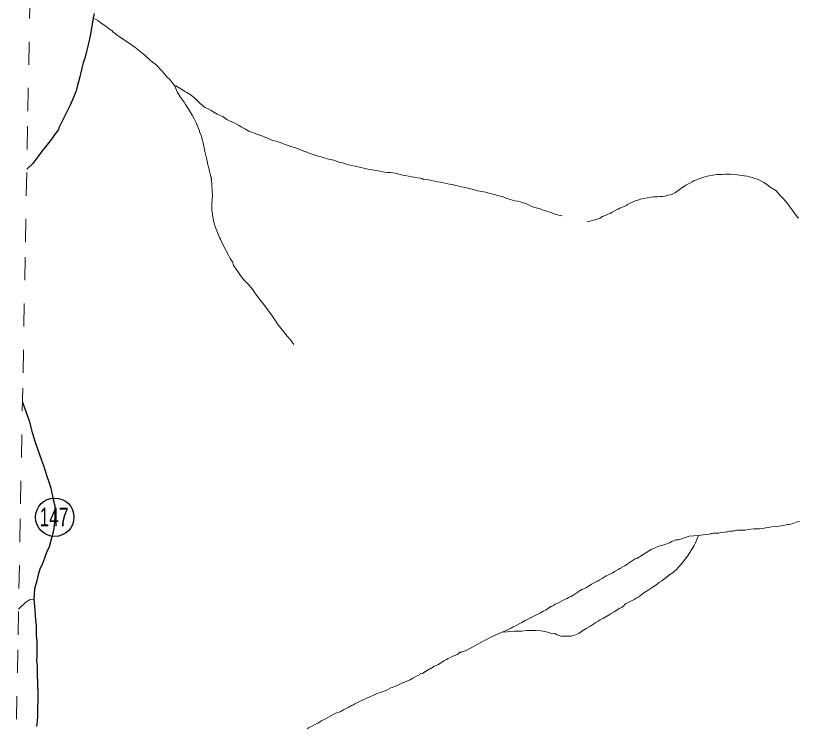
# Model space of a CAD drawing. Extents: x 781.9 to 808.1, y 7453.3 to 7481.5.
# Drawn here: x 782.028 to 785.41, y 7460.198 to 7463.258 of the extents above; entities that cross this region are included whole.
import ezdxf
from ezdxf.enums import TextEntityAlignment as Align

# ---------------------------------------------------------------- set-up
doc = ezdxf.new("R2010")
doc.units = 0
doc.header["$LTSCALE"] = 0.032
for name, pattern in [('DOTTED', [1.5, 0.3, -1.2]), ('LONG_DASHED', [7.5, 6, -1.5]), ('MEDIUM_DASHED', [4.5, 3, -1.5]), ('SHORT_DASHED', [2.7, 1.5, -1.2])]:
    doc.linetypes.add(name, pattern=pattern)
for name, color, linetype, lineweight in [('13', 7, 'Continuous', 25), ('35', 7, 'SHORT_DASHED', 13), ('4', 7, 'LONG_DASHED', 25), ('5', 7, 'LONG_DASHED', 13), ('6', 7, 'MEDIUM_DASHED', 13), ('7', 7, 'DOTTED', 13)]:
    doc.layers.add(name, color=color, linetype=linetype, lineweight=lineweight)
doc.layers.add('61', color=7, linetype='Continuous')

msp = doc.modelspace()

# ---------------------------------------------------------------- linework, layer by layer
at = {"layer": '13'}
msp.add_circle((782.1971, 7461.0924), 0.083, dxfattribs=at)
msp.add_circle((782.1971, 7461.0924), 0.083, dxfattribs=at)
msp.add_circle((782.1971, 7461.0924), 0.083, dxfattribs=at)
at = {"layer": '35'}
msp.add_lwpolyline([(782.0281, 7460.0199), (782.0387, 7460.5852), (782.0493, 7461.1504), (782.0599, 7461.7157), (782.0704, 7462.2809), (782.081, 7462.8462), (782.0916, 7463.4115), (782.1022, 7463.9767), (782.1127, 7464.542), (782.1233, 7465.1072), (782.1339, 7465.6725), (782.1444, 7466.2377), (782.155, 7466.803), (782.1655, 7467.3682)], dxfattribs=at)
at = {"layer": '4'}
for points in [[(782.367, 7463.2683), (782.3634, 7463.2487)], [(782.3634, 7463.2487), (782.3518, 7463.1787), (782.3451, 7463.1517), (782.3402, 7463.1274), (782.3337, 7463.1031), (782.328, 7463.0788), (782.3199, 7463.0545), (782.3134, 7463.0318), (782.3078, 7463.0074), (782.3021, 7462.9831), (782.2948, 7462.9588), (782.2891, 7462.9345), (782.281, 7462.9118), (782.2634, 7462.8726), (782.2482, 7462.8406), (782.2154, 7462.7742), (782.2137, 7462.7666), (782.2064, 7462.7569), (782.1991, 7462.748), (782.1829, 7462.7245), (782.1634, 7462.6993), (782.1432, 7462.6742), (782.1237, 7462.6482), (782.1026, 7462.6207), (782.0763, 7462.5962)], [(782.0575, 7461.5895), (782.0724, 7461.5495), (782.086, 7461.5087), (782.0988, 7461.4583), (782.1132, 7461.4119), (782.1221, 7461.3875), (782.131, 7461.3632), (782.1391, 7461.3389), (782.148, 7461.3162), (782.1562, 7461.2935), (782.1634, 7461.2692), (782.1715, 7461.2448), (782.1797, 7461.2177), (782.1909, 7461.1697), (782.1973, 7461.1417), (782.1981, 7461.0913), (782.1949, 7461.0585), (782.1916, 7461.0337), (782.1836, 7461.0019), (782.1723, 7460.9643), (782.1618, 7460.94), (782.1529, 7460.9157), (782.1448, 7460.893), (782.1326, 7460.8686), (782.1253, 7460.8443), (782.1189, 7460.8183), (782.11, 7460.7831), (782.106, 7460.7383)], [(782.106, 7460.7383), (782.1116, 7460.6903), (782.1131, 7460.6692), (782.114, 7460.6481), (782.1172, 7460.627), (782.1172, 7460.606), (782.1164, 7460.5881), (782.1164, 7460.5816), (782.1189, 7460.5573), (782.1189, 7460.5346), (782.1189, 7460.5135), (782.1189, 7460.4924), (782.118, 7460.4714), (782.1205, 7460.4503), (782.1213, 7460.4276), (782.1213, 7460.4049), (782.1221, 7460.3838), (782.1229, 7460.3627), (782.1245, 7460.3416), (782.1237, 7460.3189), (782.1237, 7460.2962), (782.1229, 7460.2752), (782.1221, 7460.2541), (782.1229, 7460.233), (782.1205, 7460.2119), (782.118, 7460.1892)]]:
    msp.add_lwpolyline(points, dxfattribs=at)
at = {"layer": '5'}
msp.add_lwpolyline([(782.106, 7460.7383), (782.0907, 7460.7367), (782.0721, 7460.7258), (782.0408, 7460.6955)], dxfattribs=at)
at = {"layer": '6'}
for points in [[(782.3634, 7463.2487), (782.3834, 7463.2375), (782.4018, 7463.2239), (782.4172, 7463.2125), (782.4326, 7463.202), (782.4399, 7463.1963), (782.4432, 7463.1939), (782.4488, 7463.1874), (782.4504, 7463.1874), (782.4683, 7463.1728), (782.4837, 7463.1623), (782.4991, 7463.1525), (782.5137, 7463.1428), (782.5291, 7463.1331), (782.5437, 7463.1225), (782.564, 7463.1055), (782.5859, 7463.0877), (782.5923, 7463.082), (782.6061, 7463.0698), (782.6199, 7463.0577), (782.6337, 7463.048), (782.6617, 7463.0194), (782.6833, 7462.9922), (782.6928, 7462.9838), (782.7145, 7462.9565)], [(782.7145, 7462.9565), (782.7269, 7462.9264), (782.7431, 7462.9028), (782.7569, 7462.885), (782.7626, 7462.8745), (782.7731, 7462.8583), (782.7829, 7462.8437), (782.7909, 7462.8291), (782.7991, 7462.8136), (782.8088, 7462.7958), (782.821, 7462.7634), (782.8242, 7462.7545), (782.8307, 7462.7383), (782.8339, 7462.7237), (782.838, 7462.7091), (782.8412, 7462.6945), (782.8453, 7462.6718), (782.8534, 7462.6434), (782.8558, 7462.6296), (782.8582, 7462.615), (782.8632, 7462.6004), (782.8664, 7462.5858), (782.8696, 7462.5712), (782.8712, 7462.5615), (782.8745, 7462.5591), (782.8745, 7462.5534), (782.8736, 7462.5526), (782.8753, 7462.5356), (782.8761, 7462.5299), (782.8777, 7462.5031), (782.8793, 7462.4788), (782.8777, 7462.4626), (782.8761, 7462.4464), (782.8761, 7462.4318), (782.8761, 7462.4172), (782.8785, 7462.4026), (782.8794, 7462.3985), (782.885, 7462.3669), (782.8915, 7462.3442), (782.8972, 7462.3296), (782.9036, 7462.315), (782.9093, 7462.3004), (782.9126, 7462.2931), (782.9256, 7462.2648), (782.9393, 7462.2405), (782.9483, 7462.2242), (782.9555, 7462.2096), (782.9645, 7462.195), (782.9693, 7462.1805), (782.9693, 7462.1796), (782.9888, 7462.1537), (783.0026, 7462.1318), (783.0147, 7462.1172), (783.0334, 7462.0986), (783.0496, 7462.0783), (783.0618, 7462.0621), (783.082, 7462.0345), (783.1001, 7462.0108), (783.137, 7461.9619), (783.1623, 7461.9238), (783.1907, 7461.887), (783.2012, 7461.8748), (783.2166, 7461.8578), (783.2263, 7461.8448), (783.2304, 7461.8391)], [(782.7145, 7462.9565), (782.7209, 7462.9554), (782.7353, 7462.9474), (782.7538, 7462.9356), (782.7624, 7462.9297), (782.7675, 7462.9271), (782.7869, 7462.9158), (782.8039, 7462.9004), (782.812, 7462.8923), (782.8243, 7462.8801), (782.8372, 7462.8696), (782.8469, 7462.8623), (782.8599, 7462.8558), (782.8729, 7462.8493), (782.885, 7462.8412), (782.8988, 7462.8331), (782.9223, 7462.8234), (782.9296, 7462.8185), (782.9409, 7462.8104), (782.9507, 7462.8047), (782.9637, 7462.7998), (782.9774, 7462.7925), (782.9904, 7462.7853), (783.0026, 7462.7788), (783.022, 7462.769), (783.0358, 7462.7601), (783.0399, 7462.7585), (783.0529, 7462.7536), (783.0658, 7462.7488), (783.0788, 7462.7439), (783.0918, 7462.739), (783.1048, 7462.7334), (783.1177, 7462.7293), (783.1323, 7462.7228), (783.1526, 7462.7164), (783.1631, 7462.7131), (783.1761, 7462.7099), (783.1891, 7462.7042), (783.2053, 7462.6985), (783.2166, 7462.6936), (783.2328, 7462.6888), (783.2442, 7462.6847), (783.2637, 7462.6782), (783.2807, 7462.671), (783.2831, 7462.6701), (783.2961, 7462.6653), (783.3091, 7462.6604), (783.322, 7462.6563), (783.335, 7462.6523), (783.348, 7462.649), (783.361, 7462.6442), (783.3804, 7462.6393), (783.4023, 7462.6345), (783.4145, 7462.6304), (783.4274, 7462.6247), (783.4404, 7462.6223), (783.4534, 7462.6182), (783.4664, 7462.615), (783.4793, 7462.6117), (783.4955, 7462.6085), (783.5134, 7462.6036), (783.5385, 7462.5988), (783.5442, 7462.5972), (783.5572, 7462.5947), (783.5701, 7462.5923), (783.5831, 7462.5898), (783.5961, 7462.5882), (783.609, 7462.585), (783.622, 7462.5826), (783.635, 7462.5817), (783.648, 7462.5809)], [(783.648, 7462.5809), (783.6674, 7462.5785), (783.6958, 7462.5712), (783.6999, 7462.5704), (783.7128, 7462.568), (783.7258, 7462.5655), (783.7388, 7462.5631)], [(783.7388, 7462.5631), (783.7517, 7462.5615), (783.7647, 7462.5582), (783.7777, 7462.5574), (783.7834, 7462.555), (783.785, 7462.5542), (783.7866, 7462.5526), (783.7923, 7462.5517), (783.8206, 7462.5477), (783.8247, 7462.5469), (783.8377, 7462.5436), (783.8507, 7462.5412), (783.8636, 7462.5388), (783.8766, 7462.5372), (783.8896, 7462.5339), (783.9025, 7462.5315), (783.9155, 7462.529), (783.9298, 7462.5255), (783.9818, 7462.5135), (784.0002, 7462.5087), (784.0258, 7462.5023), (784.042, 7462.4991), (784.0582, 7462.4958), (784.0728, 7462.4918), (784.0955, 7462.4861), (784.1223, 7462.4796), (784.1344, 7462.4755), (784.1506, 7462.4691), (784.1669, 7462.465), (784.1831, 7462.4593), (784.1977, 7462.4577), (784.2123, 7462.4537), (784.235, 7462.4455), (784.2617, 7462.4334), (784.2771, 7462.4285), (784.2941, 7462.4236), (784.3079, 7462.418), (784.3225, 7462.4139), (784.3411, 7462.4082), (784.3598, 7462.4018), (784.3809, 7462.3961), (784.3898, 7462.3937)], [(785.4113, 7462.3839), (785.4049, 7462.3904), (785.387, 7462.4155), (785.3741, 7462.4326), (785.3635, 7462.448), (785.3554, 7462.4569), (785.3441, 7462.4691), (785.3327, 7462.4804), (785.3246, 7462.4901), (785.3125, 7462.5039), (785.2881, 7462.5185), (785.2727, 7462.5307), (785.2606, 7462.538), (785.2484, 7462.5453), (785.2378, 7462.5509), (785.2225, 7462.5558), (785.2111, 7462.5591), (785.1998, 7462.5631), (785.1884, 7462.5647), (785.177, 7462.5663), (785.1746, 7462.5664), (785.1479, 7462.5712), (785.13, 7462.5728), (785.1171, 7462.5745), (785.1041, 7462.5745), (785.0927, 7462.5745), (785.0814, 7462.5728), (785.07, 7462.572), (785.0587, 7462.572), (785.0498, 7462.5712), (785.0165, 7462.5655), (785.0019, 7462.5607), (784.9938, 7462.5582), (784.9809, 7462.5542), (784.9695, 7462.5501), (784.959, 7462.5453), (784.9508, 7462.5404), (784.9419, 7462.5356), (784.933, 7462.5307), (784.9241, 7462.5258), (784.92, 7462.5234), (784.8965, 7462.5071), (784.8795, 7462.4942), (784.8682, 7462.4885), (784.8576, 7462.4853), (784.8463, 7462.4828), (784.8349, 7462.4796), (784.8236, 7462.478), (784.8122, 7462.4772), (784.8009, 7462.4763), (784.7879, 7462.4763), (784.7838, 7462.4756), (784.7587, 7462.4723), (784.7393, 7462.4691), (784.7279, 7462.4658), (784.7166, 7462.4618), (784.7052, 7462.4585), (784.6939, 7462.4537), (784.6825, 7462.4488), (784.6727, 7462.4423), (784.6671, 7462.4383), (784.6436, 7462.4293), (784.6379, 7462.4277), (784.6314, 7462.4228), (784.6257, 7462.4212), (784.616, 7462.4155), (784.6063, 7462.4099), (784.5965, 7462.4042), (784.5868, 7462.4009), (784.5755, 7462.3953), (784.5641, 7462.3912), (784.552, 7462.3847), (784.5406, 7462.3791), (784.5155, 7462.3726), (784.496, 7462.3685)]]:
    msp.add_lwpolyline(points, dxfattribs=at)
at = {"layer": '7'}
for points in [[(785.4154, 7461.0745), (785.4057, 7461.0721), (785.3911, 7461.0664), (785.3724, 7461.0616), (785.3668, 7461.0608), (785.3571, 7461.0591), (785.3473, 7461.0567), (785.336, 7461.0551), (785.3198, 7461.0527), (785.2946, 7461.0503), (785.2792, 7461.0478), (785.2679, 7461.047), (785.2581, 7461.0445), (785.2419, 7461.0421), (785.2184, 7461.0429), (785.2046, 7461.0413), (785.1933, 7461.0389), (785.1811, 7461.0368), (785.1438, 7461.0364), (785.1365, 7461.0332), (785.13, 7461.0332), (785.1244, 7461.0324), (785.1187, 7461.0316), (785.1122, 7461.0316), (785.1057, 7461.0299), (785.1024, 7461.0292), (785.0992, 7461.0291), (785.0919, 7461.0275), (785.0733, 7461.0259), (785.0668, 7461.0243), (785.0619, 7461.0235), (785.0555, 7461.0235), (785.049, 7461.0235), (785.0425, 7461.0235), (785.036, 7461.0218), (785.0343, 7461.0226), (785.0327, 7461.021), (785.0295, 7461.021), (785.0254, 7461.0194), (785.0084, 7461.0178), (784.9783, 7461.0134)], [(784.9783, 7461.0134), (784.9646, 7460.9797), (784.9597, 7460.9708), (784.9516, 7460.9554), (784.9387, 7460.9359), (784.9338, 7460.9286), (784.9273, 7460.9189), (784.9152, 7460.9043), (784.903, 7460.8889), (784.8949, 7460.88), (784.8819, 7460.8654), (784.8649, 7460.8516), (784.8625, 7460.85), (784.8544, 7460.8451), (784.839, 7460.8321), (784.8211, 7460.8192), (784.8203, 7460.8184), (784.8098, 7460.8118), (784.7944, 7460.7997), (784.7741, 7460.7859), (784.766, 7460.781), (784.7571, 7460.7745), (784.7425, 7460.7656), (784.7206, 7460.7486), (784.7101, 7460.7429), (784.7036, 7460.7389), (784.7003, 7460.7373), (784.6979, 7460.7358), (784.6638, 7460.7186), (784.659, 7460.7138), (784.6565, 7460.7113), (784.6557, 7460.7089), (784.65, 7460.7073), (784.65, 7460.7064), (784.6468, 7460.7024), (784.6403, 7460.7), (784.6395, 7460.7), (784.6144, 7460.6837), (784.6014, 7460.6773), (784.5933, 7460.6716), (784.586, 7460.6667), (784.5681, 7460.6562), (784.5544, 7460.6497), (784.5448, 7460.644), (784.5349, 7460.6375), (784.5309, 7460.6351), (784.509, 7460.6213), (784.496, 7460.614), (784.4887, 7460.6084), (784.4814, 7460.6051), (784.479, 7460.6035), (784.4612, 7460.5905), (784.4474, 7460.5848), (784.4376, 7460.5816), (784.4279, 7460.5783), (784.4182, 7460.5784), (784.4141, 7460.5784), (784.3906, 7460.5783), (784.3858, 7460.5783), (784.3793, 7460.58), (784.3768, 7460.5824), (784.3728, 7460.5832), (784.3695, 7460.584), (784.3679, 7460.5849), (784.3647, 7460.5865), (784.3574, 7460.5897), (784.3387, 7460.5921), (784.3258, 7460.5962), (784.316, 7460.5986), (784.3063, 7460.6002), (784.2974, 7460.6019), (784.2755, 7460.6027), (784.2609, 7460.6027), (784.2528, 7460.6027), (784.2447, 7460.6027), (784.2374, 7460.6027), (784.2139, 7460.6011), (784.2009, 7460.601), (784.1912, 7460.6011), (784.1839, 7460.6011), (784.1514, 7460.5975), (784.1311, 7460.596)], [(784.9783, 7461.0134), (784.9382, 7461.0102), (784.8929, 7460.9954), (784.8884, 7460.9951), (784.8836, 7460.9951), (784.8827, 7460.9951), (784.8625, 7460.987), (784.8543, 7460.9821), (784.8495, 7460.9805), (784.8414, 7460.9772), (784.8333, 7460.9748), (784.8244, 7460.9724), (784.8074, 7460.9675), (784.7968, 7460.9635), (784.7911, 7460.961), (784.783, 7460.9578), (784.7749, 7460.9529), (784.7668, 7460.9481), (784.7579, 7460.9432), (784.7393, 7460.931), (784.7279, 7460.9237), (784.7198, 7460.9189), (784.7125, 7460.914), (784.7052, 7460.9132), (784.7044, 7460.9124), (784.6792, 7460.8954), (784.6663, 7460.8872), (784.6598, 7460.8832), (784.6517, 7460.8783), (784.642, 7460.8727), (784.6347, 7460.8686), (784.616, 7460.8581), (784.6055, 7460.8508), (784.5982, 7460.8475), (784.5901, 7460.8435), (784.582, 7460.8402), (784.5795, 7460.8395), (784.5625, 7460.8281), (784.5495, 7460.8208), (784.5422, 7460.8159), (784.5333, 7460.8127), (784.5252, 7460.8078), (784.5171, 7460.8029), (784.5147, 7460.8013), (784.4952, 7460.7892), (784.4831, 7460.7835), (784.4749, 7460.7802), (784.4668, 7460.7754), (784.4595, 7460.7705), (784.4579, 7460.7689)], [(784.4579, 7460.7689), (784.44, 7460.7575), (784.4279, 7460.7502), (784.4198, 7460.747), (784.4109, 7460.7421), (784.402, 7460.7381), (784.3995, 7460.7365)], [(784.3995, 7460.7365), (784.3793, 7460.7259), (784.3679, 7460.7202), (784.3598, 7460.717), (784.3517, 7460.7113), (784.3436, 7460.7073), (784.3412, 7460.7065), (784.3209, 7460.6927), (784.3079, 7460.6862), (784.3006, 7460.6821), (784.2917, 7460.6773), (784.282, 7460.6724), (784.2723, 7460.6675), (784.2698, 7460.6667), (784.2496, 7460.6562), (784.2382, 7460.6505), (784.2301, 7460.6464), (784.2228, 7460.6416), (784.2155, 7460.6383), (784.2131, 7460.6368), (784.1912, 7460.6246), (784.1782, 7460.6189), (784.1693, 7460.614), (784.1612, 7460.6092), (784.1311, 7460.596)], [(784.1311, 7460.596), (784.0902, 7460.5783), (784.0352, 7460.5506), (783.977, 7460.5189), (783.9589, 7460.5105), (783.9576, 7460.5119), (783.9552, 7460.5102), (783.9504, 7460.5102), (783.9496, 7460.5086), (783.9455, 7460.5078), (783.9423, 7460.5046), (783.9374, 7460.4997), (783.9147, 7460.4908), (783.9049, 7460.4859), (783.8977, 7460.4819), (783.8896, 7460.4786), (783.8815, 7460.4738), (783.879, 7460.4722), (783.8636, 7460.4624), (783.8523, 7460.4551), (783.8442, 7460.4519), (783.8361, 7460.4486), (783.8288, 7460.4438), (783.8215, 7460.4397), (783.8174, 7460.4373), (783.7996, 7460.4259), (783.7874, 7460.4186), (783.7858, 7460.417), (783.7777, 7460.4162), (783.7752, 7460.4154), (783.7736, 7460.4121), (783.7704, 7460.4105), (783.7631, 7460.4073), (783.7607, 7460.4057), (783.7444, 7460.3975), (783.7323, 7460.3902), (783.7242, 7460.387), (783.7161, 7460.3838), (783.708, 7460.3805), (783.7023, 7460.3781), (783.6674, 7460.3611), (783.6577, 7460.3587), (783.6545, 7460.3578), (783.6488, 7460.3562), (783.6293, 7460.3448), (783.6228, 7460.3424), (783.6204, 7460.3416), (783.6147, 7460.3392), (783.609, 7460.3367), (783.5993, 7460.3343), (783.5936, 7460.3327), (783.5718, 7460.323), (783.5588, 7460.3173), (783.5491, 7460.3132), (783.5393, 7460.3084), (783.532, 7460.3051), (783.5077, 7460.2938), (783.4939, 7460.2865), (783.485, 7460.2808), (783.4761, 7460.2776), (783.4672, 7460.2727), (783.4445, 7460.2605), (783.4307, 7460.2524), (783.421, 7460.2492), (783.4112, 7460.2459), (783.4031, 7460.2419), (783.4007, 7460.2411), (783.3772, 7460.2273), (783.3642, 7460.2208), (783.3561, 7460.2167), (783.348, 7460.2127)], [(783.348, 7460.2127), (783.3407, 7460.2078), (783.3334, 7460.2038), (783.3293, 7460.2022), (783.3099, 7460.19), (783.2961, 7460.1843), (783.288, 7460.1794)]]:
    msp.add_lwpolyline(points, dxfattribs=at)

# ---------------------------------------------------------------- texts
at = {"layer": '61', "width": 0.7}
msp.add_text('147', height=0.08, dxfattribs=at).set_placement((782.194, 7461.0533), align=Align.CENTER)

doc.saveas('drawing.dxf')
